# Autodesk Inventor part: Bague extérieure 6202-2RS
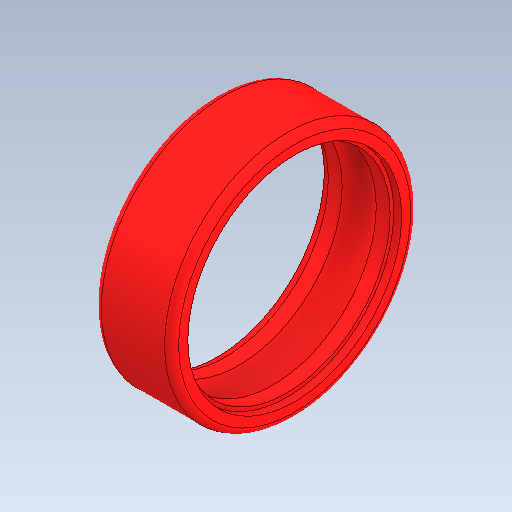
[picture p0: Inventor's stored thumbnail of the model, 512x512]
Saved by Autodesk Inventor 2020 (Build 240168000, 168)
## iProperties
Created: 2003-06
Part Number: Bague extérieure 6202-2RS
Material: Générique
Document SubType Name: Modeling
Designer: Bruno
Density: 1 g/cm^3
Appearance: Par défaut
Author: Bruno
Sending System: SolidWorks 2011
Last Author: frederic
Last Saved: 2012-02-20
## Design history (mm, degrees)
feature "Base-Révolution"
node "Solide1"
